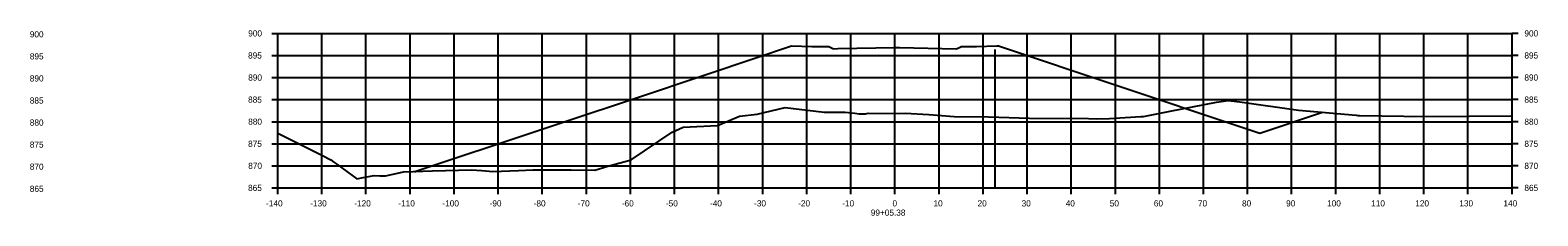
# Model space of a CAD drawing. Extents: x 1098669 to 1198896, y 698679 to 704410.
# Drawn here: x 1110759.2 to 1111101.3, y 700200.9 to 700243 of the extents above; entities that cross this region are included whole.
import ezdxf

# ---------------------------------------------------------------- set-up
doc = ezdxf.new("R2010")
doc.units = 0
for name, color, linetype in [('R_Alt Surface', 7, 'Continuous'), ('R_Axis', 7, 'Continuous'), ('R_Axis Annot', 7, 'Continuous'), ('R_Fin Surface', 7, 'Continuous'), ('R_Grid', 7, 'Continuous')]:
    doc.layers.add(name, color=color, linetype=linetype)

msp = doc.modelspace()

# ---------------------------------------------------------------- linework, layer by layer
at = {"layer": 'R_Alt Surface'}
msp.add_lwpolyline([(1110815.43, 700219.62), (1110825.4, 700214.63), (1110827.42, 700213.56), (1110828.12, 700213.09), (1110828.85, 700212.64), (1110833.37, 700209.32), (1110834.82, 700209.56), (1110837.29, 700210.06), (1110838.57, 700210), (1110839.89, 700209.93), (1110841.57, 700210.35), (1110843.97, 700210.86), (1110850.49, 700211.06), (1110859.34, 700211.31), (1110861.73, 700211.14), (1110864.24, 700210.96), (1110870.01, 700211.18), (1110873.27, 700211.36), (1110880.87, 700211.33), (1110881.48, 700211.33), (1110881.8, 700211.33), (1110881.99, 700211.34), (1110887.34, 700211.28), (1110890.29, 700212.13), (1110895.59, 700213.62), (1110904.91, 700219.82), (1110907.35, 700221), (1110915.17, 700221.33), (1110920.2, 700223.48), (1110924.16, 700223.97), (1110930.5, 700225.48), (1110939.35, 700224.35), (1110944.16, 700224.42), (1110946.33, 700224.19), (1110947.28, 700224), (1110948.74, 700224.03), (1110949.36, 700224.14), (1110956.3, 700224.05), (1110957.73, 700224.13), (1110963.12, 700223.85), (1110968.83, 700223.44), (1110976.64, 700223.31), (1110985.96, 700222.99), (1110999.32, 700222.94), (1111001.25, 700222.89), (1111004.14, 700222.93), (1111011.18, 700223.41), (1111011.78, 700223.43), (1111017.86, 700224.64), (1111028.36, 700226.67), (1111031, 700227.02), (1111033.66, 700226.71), (1111047, 700224.83), (1111060.09, 700223.69), (1111060.48, 700223.64), (1111060.57, 700223.61), (1111060.79, 700223.61), (1111075.96, 700223.38), (1111095.43, 700223.58)], dxfattribs=at)
at = {"layer": 'R_Axis'}
for p, q in [((1110814.03, 700242.23), (1110815.43, 700242.23)), ((1110815.43, 700207.23), (1110815.43, 700242.23)), ((1111095.43, 700207.23), (1111095.43, 700242.23)), ((1111096.83, 700242.23), (1111095.43, 700242.23)), ((1110814.03, 700237.23), (1110815.43, 700237.23)), ((1111096.83, 700237.23), (1111095.43, 700237.23)), ((1110814.03, 700232.23), (1110815.43, 700232.23)), ((1111096.83, 700232.23), (1111095.43, 700232.23)), ((1110814.03, 700227.23), (1110815.43, 700227.23)), ((1111096.83, 700227.23), (1111095.43, 700227.23)), ((1110814.03, 700222.23), (1110815.43, 700222.23)), ((1111096.83, 700222.23), (1111095.43, 700222.23)), ((1110814.03, 700217.23), (1110815.43, 700217.23)), ((1111096.83, 700217.23), (1111095.43, 700217.23)), ((1110814.03, 700212.23), (1110815.43, 700212.23)), ((1111096.83, 700212.23), (1111095.43, 700212.23)), ((1110814.03, 700207.23), (1110815.43, 700207.23)), ((1110815.43, 700207.23), (1111095.43, 700207.23)), ((1110815.43, 700205.83), (1110815.43, 700207.23)), ((1110825.43, 700205.83), (1110825.43, 700207.23)), ((1110835.43, 700205.83), (1110835.43, 700207.23)), ((1110845.43, 700205.83), (1110845.43, 700207.23)), ((1110855.43, 700205.83), (1110855.43, 700207.23)), ((1110865.43, 700205.83), (1110865.43, 700207.23)), ((1110875.43, 700205.83), (1110875.43, 700207.23)), ((1110885.43, 700205.83), (1110885.43, 700207.23)), ((1110895.43, 700205.83), (1110895.43, 700207.23)), ((1110905.43, 700205.83), (1110905.43, 700207.23)), ((1110915.43, 700205.83), (1110915.43, 700207.23)), ((1110925.43, 700205.83), (1110925.43, 700207.23)), ((1110935.43, 700205.83), (1110935.43, 700207.23)), ((1110945.43, 700205.83), (1110945.43, 700207.23)), ((1110955.43, 700205.83), (1110955.43, 700207.23)), ((1110965.43, 700205.83), (1110965.43, 700207.23)), ((1110975.43, 700205.83), (1110975.43, 700207.23)), ((1110985.43, 700205.83), (1110985.43, 700207.23)), ((1110995.43, 700205.83), (1110995.43, 700207.23)), ((1111005.43, 700205.83), (1111005.43, 700207.23)), ((1111015.43, 700205.83), (1111015.43, 700207.23)), ((1111025.43, 700205.83), (1111025.43, 700207.23)), ((1111035.43, 700205.83), (1111035.43, 700207.23)), ((1111045.43, 700205.83), (1111045.43, 700207.23)), ((1111055.43, 700205.83), (1111055.43, 700207.23)), ((1111065.43, 700205.83), (1111065.43, 700207.23)), ((1111075.43, 700205.83), (1111075.43, 700207.23)), ((1111085.43, 700205.83), (1111085.43, 700207.23)), ((1111095.43, 700205.83), (1111095.43, 700207.23)), ((1111096.83, 700207.23), (1111095.43, 700207.23))]:
    msp.add_line(p, q, dxfattribs=at)
at = {"layer": 'R_Fin Surface'}
msp.add_lwpolyline([(1110846.43, 700210.89), (1110846.63, 700210.95), (1110846.69, 700210.97), (1110846.73, 700210.99), (1110902.69, 700229.62), (1110906.25, 700230.8), (1110908.97, 700231.71), (1110927.27, 700237.82), (1110928.09, 700238.1), (1110929.47, 700238.56), (1110931.93, 700239.39), (1110936.55, 700239.29), (1110936.93, 700239.29), (1110937.16, 700239.28), (1110939.93, 700239.23), (1110940.39, 700239.23), (1110940.43, 700239.23), (1110941.35, 700238.78), (1110941.43, 700238.75), (1110942.49, 700238.77), (1110955.43, 700239.03), (1110956.49, 700239.01), (1110969.43, 700238.75), (1110970.35, 700239.19), (1110970.43, 700239.23), (1110970.89, 700239.23), (1110970.93, 700239.23), (1110971.16, 700239.23), (1110973.93, 700239.29), (1110978.55, 700239.38), (1110978.93, 700239.39), (1111033.69, 700221.14), (1111038.21, 700219.63), (1111039.12, 700219.93), (1111052.4, 700224.36)], dxfattribs=at)
at = {"layer": 'R_Grid'}
for p, q in [((1110815.43, 700242.23), (1111095.43, 700242.23)), ((1110815.43, 700207.23), (1110815.43, 700242.23)), ((1110825.43, 700207.23), (1110825.43, 700242.23)), ((1110835.43, 700207.23), (1110835.43, 700242.23)), ((1110845.43, 700207.23), (1110845.43, 700242.23)), ((1110855.43, 700207.23), (1110855.43, 700242.23)), ((1110865.43, 700207.23), (1110865.43, 700242.23)), ((1110875.43, 700207.23), (1110875.43, 700242.23)), ((1110885.43, 700207.23), (1110885.43, 700242.23)), ((1110895.43, 700207.23), (1110895.43, 700242.23)), ((1110905.43, 700207.23), (1110905.43, 700242.23)), ((1110915.43, 700207.23), (1110915.43, 700242.23)), ((1110925.43, 700207.23), (1110925.43, 700242.23)), ((1110935.43, 700207.23), (1110935.43, 700242.23)), ((1110945.43, 700207.23), (1110945.43, 700242.23)), ((1110955.43, 700207.23), (1110955.43, 700242.23)), ((1110965.43, 700207.23), (1110965.43, 700242.23)), ((1110975.43, 700207.23), (1110975.43, 700242.23)), ((1110985.43, 700207.23), (1110985.43, 700242.23)), ((1110995.43, 700207.23), (1110995.43, 700242.23)), ((1111005.43, 700207.23), (1111005.43, 700242.23)), ((1111015.43, 700207.23), (1111015.43, 700242.23)), ((1111025.43, 700207.23), (1111025.43, 700242.23)), ((1111035.43, 700207.23), (1111035.43, 700242.23)), ((1111045.43, 700207.23), (1111045.43, 700242.23)), ((1111055.43, 700207.23), (1111055.43, 700242.23)), ((1111065.43, 700207.23), (1111065.43, 700242.23)), ((1111075.43, 700207.23), (1111075.43, 700242.23)), ((1111085.43, 700207.23), (1111085.43, 700242.23)), ((1111095.43, 700207.23), (1111095.43, 700242.23)), ((1110815.43, 700237.23), (1111095.43, 700237.23)), ((1110978.18, 700207.23), (1110978.18, 700238.57)), ((1110815.43, 700232.23), (1111095.43, 700232.23)), ((1110815.43, 700227.23), (1111095.43, 700227.23)), ((1110815.43, 700222.23), (1111095.43, 700222.23)), ((1110815.43, 700217.23), (1111095.43, 700217.23)), ((1110815.43, 700212.23), (1111095.43, 700212.23)), ((1110815.43, 700207.23), (1111095.43, 700207.23))]:
    msp.add_line(p, q, dxfattribs=at)

# ---------------------------------------------------------------- texts
at = {"layer": 'R_Axis Annot'}
for s, p in [('900', (1110759.16, 700241.33)), ('900', (1110808.71, 700241.53)), ('900', (1111098.23, 700241.53)), ('895', (1110759.16, 700236.33)), ('895', (1110808.68, 700236.53)), ('895', (1111098.23, 700236.53)), ('890', (1110759.16, 700231.33)), ('890', (1110808.71, 700231.53)), ('890', (1111098.23, 700231.53)), ('885', (1110759.16, 700226.33)), ('885', (1110808.68, 700226.53)), ('885', (1111098.23, 700226.53)), ('880', (1110759.16, 700221.33)), ('880', (1110808.71, 700221.53)), ('880', (1111098.23, 700221.53)), ('875', (1110759.16, 700216.33)), ('875', (1110808.68, 700216.53)), ('875', (1111098.23, 700216.53)), ('870', (1110759.16, 700211.33)), ('870', (1110808.71, 700211.53)), ('870', (1111098.23, 700211.53)), ('865', (1110759.16, 700206.33)), ('865', (1110808.68, 700206.53)), ('865', (1111098.23, 700206.53)), ('-140', (1110812.77, 700203.03)), ('-130', (1110822.77, 700203.03)), ('-120', (1110832.77, 700203.03)), ('-110', (1110842.77, 700203.03)), ('-100', (1110852.77, 700203.03)), ('-90', (1110863.47, 700203.03)), ('-80', (1110873.47, 700203.03)), ('-70', (1110883.47, 700203.03)), ('-60', (1110893.47, 700203.03)), ('-50', (1110903.47, 700203.03)), ('-40', (1110913.47, 700203.03)), ('-30', (1110923.47, 700203.03)), ('-20', (1110933.47, 700203.03)), ('-10', (1110943.47, 700203.03)), ('0', (1110954.87, 700203.03)), ('10', (1110964.17, 700203.03)), ('20', (1110974.17, 700203.03)), ('30', (1110984.17, 700203.03)), ('40', (1110994.17, 700203.03)), ('50', (1111004.17, 700203.03)), ('60', (1111014.17, 700203.03)), ('70', (1111024.17, 700203.03)), ('80', (1111034.17, 700203.03)), ('90', (1111044.17, 700203.03)), ('100', (1111053.47, 700203.03)), ('110', (1111063.47, 700203.03)), ('120', (1111073.47, 700203.03)), ('130', (1111083.47, 700203.03)), ('140', (1111093.47, 700203.03)), ('99+05.38', (1110949.95, 700200.93))]:
    msp.add_text(s, height=1.4, dxfattribs=at).set_placement(p)

doc.saveas('drawing.dxf')
